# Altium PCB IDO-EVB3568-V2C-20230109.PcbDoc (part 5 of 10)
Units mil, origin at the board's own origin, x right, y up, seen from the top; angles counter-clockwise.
Board outline 5318 x 3544 mil, 2 copper layers (TOP, BOTTOM), stack 6.8 mil thick; 790 components, 626 nets, 2890 pads, 1922 vias.
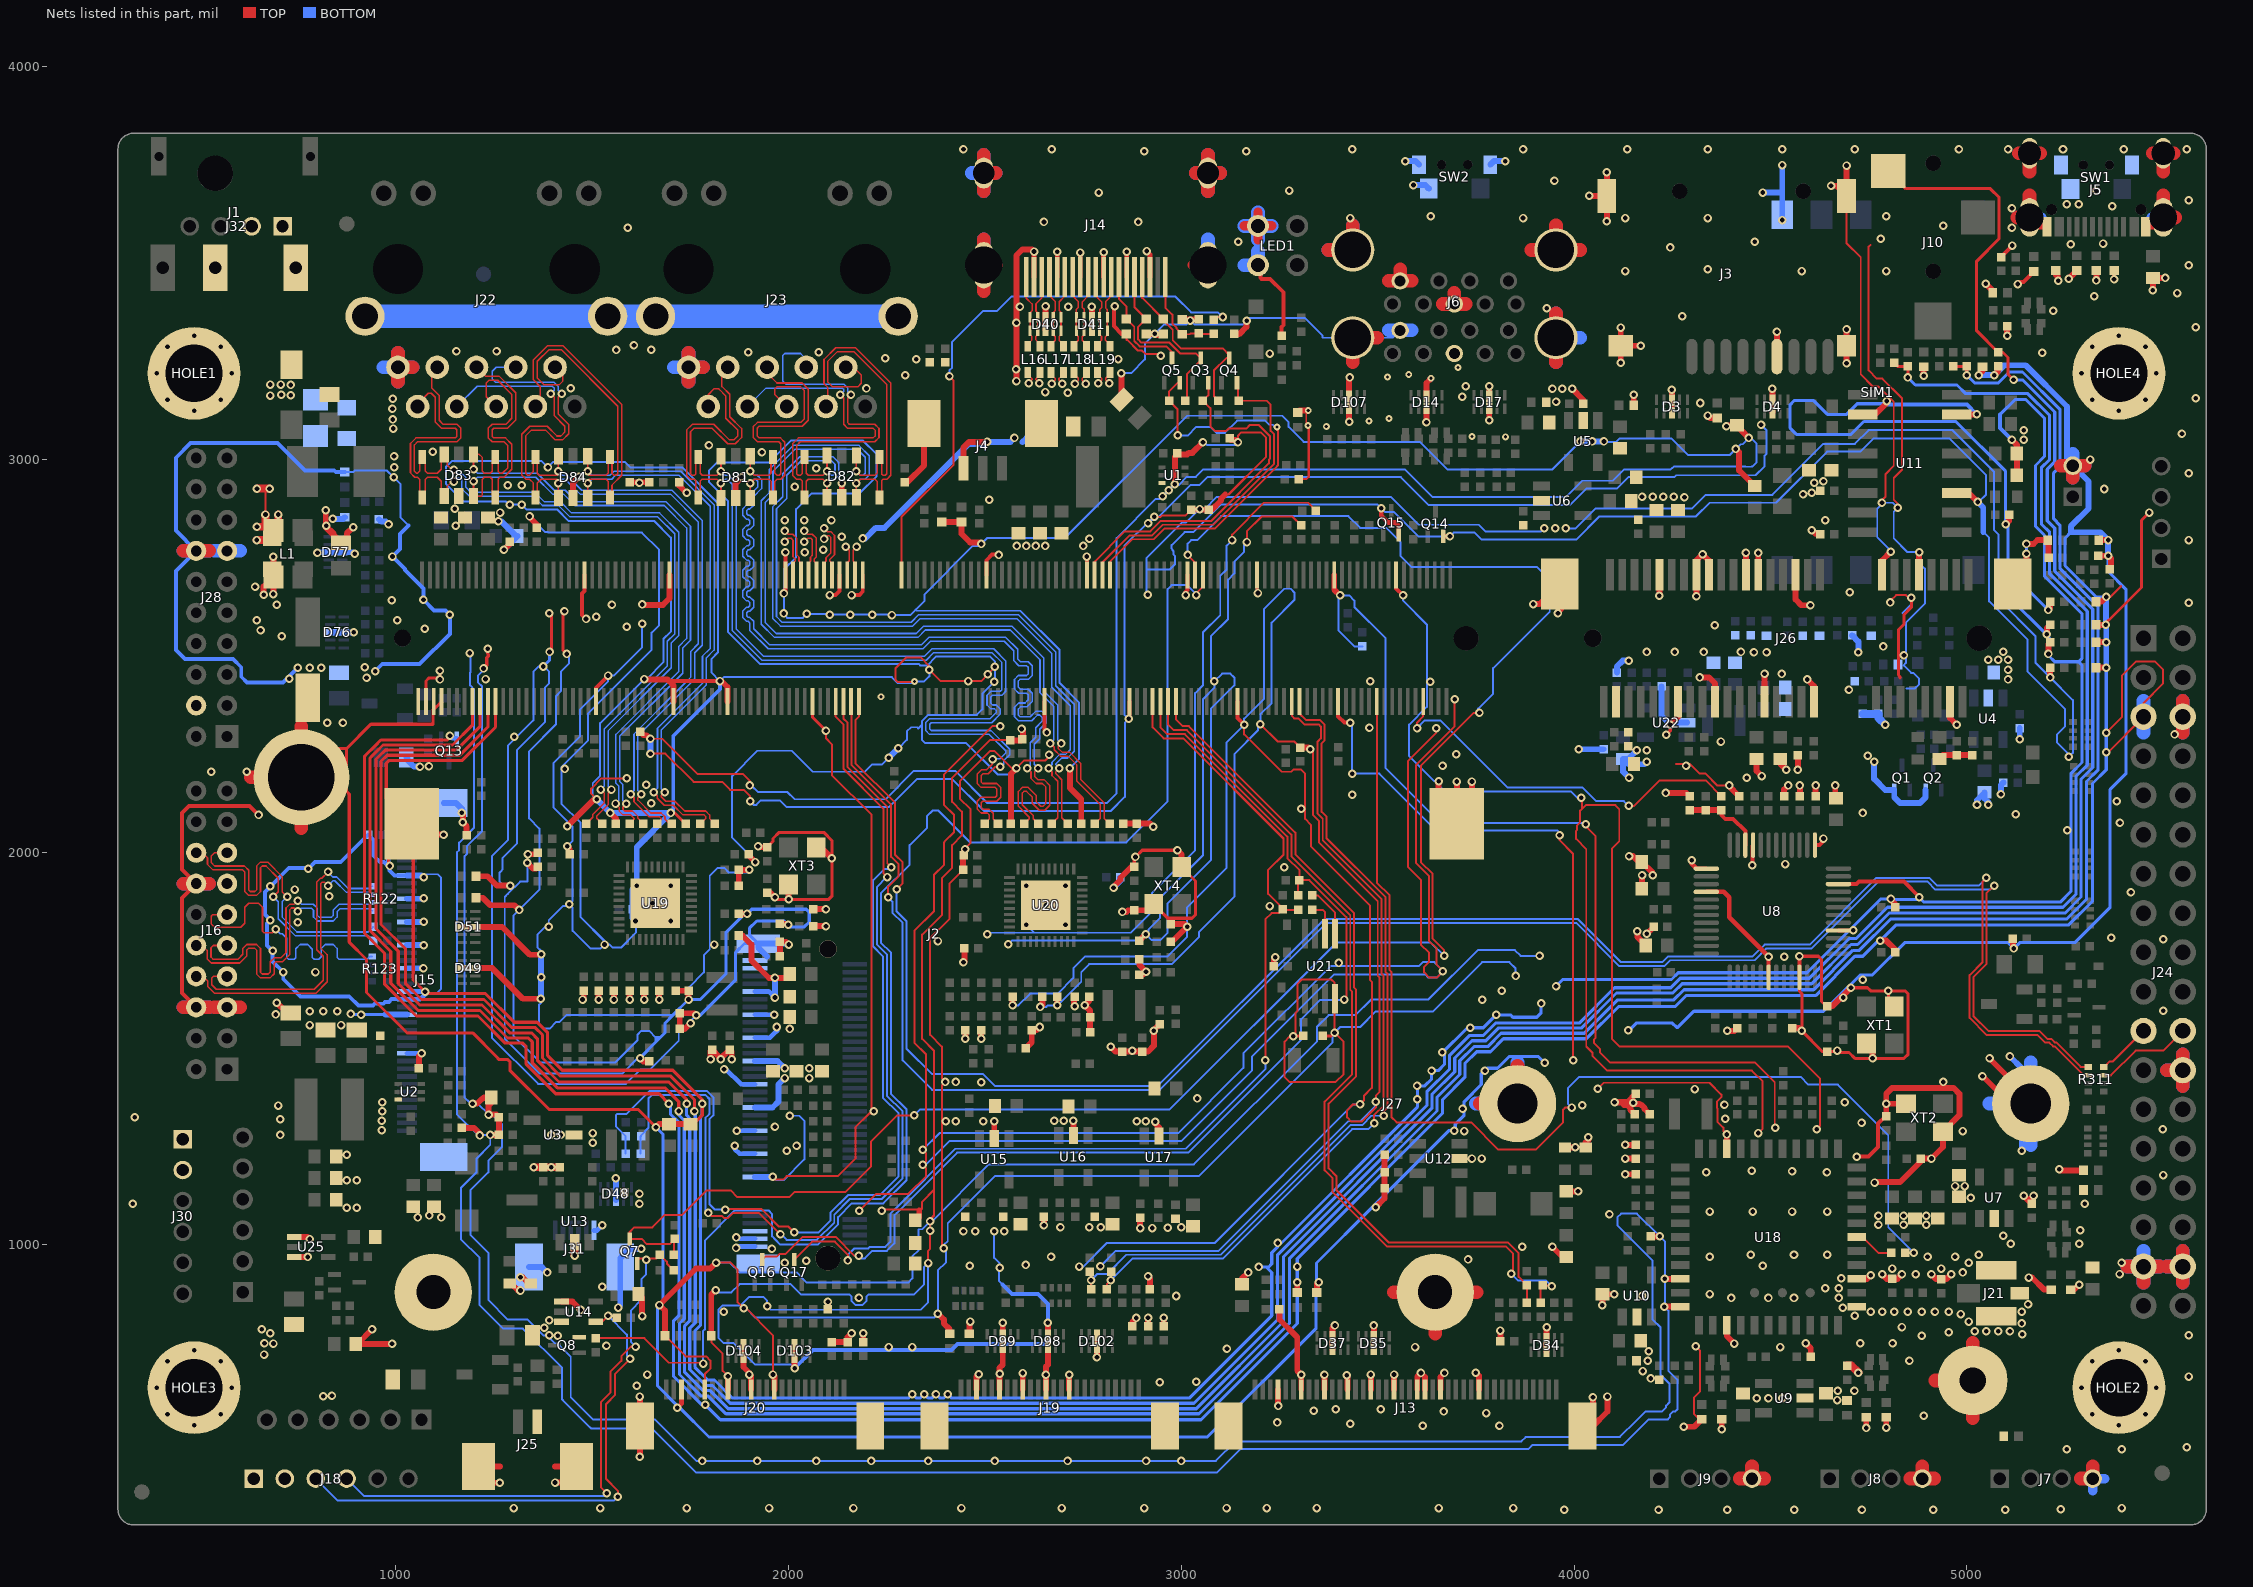
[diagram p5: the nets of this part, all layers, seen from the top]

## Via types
v1: diameter 21.65, hole 11.81, TOP to BOTTOM, 1878 vias
v2: diameter 17.72, hole 7.87, TOP to BOTTOM, 44 vias

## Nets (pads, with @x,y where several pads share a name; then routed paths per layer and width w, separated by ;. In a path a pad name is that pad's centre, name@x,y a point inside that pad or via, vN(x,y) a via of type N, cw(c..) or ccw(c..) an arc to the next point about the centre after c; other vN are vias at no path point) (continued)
GND: (continued)
  BOTTOM w12: v1(984,1965) 980.49,1968.51 980.49,1985.49 994.8,1999.8 J15.37@1027.99,1999.8 ; J15.11@1027.99,1487.99 v1(1065,1487.99) ; J15.18@1027.99,1625.79 1062,1625.79 1074,1637.79 v1(1074,1645) 1073.53,1645.47 J15.19@1027.99,1645.47 ; v1(1137.41,2296.22) 1143.13,2290.5 Q13.2@1154.68,2290.5 ; J31.6@1504.21,1037.01 1512.01,1037.01 v1(1525,1050) ; v1(1835.43,1447.71) 1840.29,1447.71 1878.79,1409.21 J27.33@1913.98,1409.21 ; v1(1863,1253) 1863,1244.05 1875,1232.05 J27.51@1913.98,1232.05 ; v1(1865.9,992.36) 1866,992.36 1869.47,995.83 J27.75@1913.98,995.83 ; v1(1866.65,1019) 1870,1019 1873.49,1015.51 J27.73@1913.98,1015.51 ; v1(1868,1291.1) J27.45@1913.98,1291.1 ; J27.21@1913.98,1527.32 1952.32,1527.32 1970,1545 v1(1970,1555) ; J27.15@1913.98,1586.38 v1(1963.62,1586.38) ; J27.9@1913.98,1645.43 1949.57,1645.43 v1(1965,1630)
  BOTTOM w15: v1(800,2763) 801,2764 D77.3@830.44,2764 D77.8@861.56,2764 891,2764 v1(895,2760) ; D76.3@834.44,2560 D76.8@865.56,2560 v1(892,2560) ; v1(839.1,2849.1) 865,2849.1 869,2853.1 D80.2@870,2853.1 ; R385.2@956.72,2848 962.72,2842 974,2842 v1(981,2835) ; 973.58,1586.42 J15.16@1027.99,1586.42 ; C245.1@1026.48,2241 1029.48,2238 1029.48,2234.52 1046,2218 v1(1061,2218) ; J15.22@1027.99,1704.53 v1(1070,1704.53) ; J15.25@1027.99,1763.58 v1(1071,1763.58) ; J15.28@1027.99,1822.64 v1(1071,1822.64) ; J15.31@1027.99,1881.69 1069,1881.69 1070,1882.69 v1(1071,1882.69) ; J15.34@1027.99,1940.75 1064.25,1940.75 1069,1936 v1(1071,1936) ; 1087,959 1095.08,950.92 J2.N4@1095.08,879.65 1095.08,860.92 1142,814 ; J15.42@1121.5,2125.79 1152.21,2125.79 1170,2108 v1(1170,2076) ; v1(1261,2843) 1268,2843 1306,2805 C26.1@1309.56,2805 1309.56,2804.56 v1(1275,2770) ; J31.7@1338.86,943.5 1371.5,943.5 v1(1385,930) ; v1(1369,1627) 1369,1676 1369.5,1676.5 v1(1369.5,1681.5) v1(1369.5,1740) ; v1(1511,2135) v1(1546,2100) v1(1700,2100) 1613,2013 v1(1613,1915) 1602.72,1904.72 C138.1@1602.72,1855 1602.72,1832.28 v1(1610,1825) ; D48.3@1560,1114.44 D48.8@1560,1145.56 v1(1560,1170) ; v1(1566,840.65) 1571,845.65 1571,857.21 1571.14,857.36 J31.8@1571.14,943.5 1571.14,966.14 1595,990 v1(1625,990) ; v1(1648,2251) v1(1648,2289) ; J27.57@1913.98,1172.99 1957.99,1172.99 v1(1958.99,1173.99) ; J27.39@1913.98,1350.16 1958.97,1350.16 1973.61,1364.79 1973.61,1408.61 v1(1990,1425) ; J27.27@1913.98,1468.27 1971.73,1468.27 v1(1990,1450) ; 1945,1735 1922.84,1757.16 J27.G2@1922.84,1767.48 1997.52,1767.48 v1(2000,1765) ; v1(1965,1630) v1(1965,1680) ; v1(2189,2799) 2195,2799 2222,2826 2244,2826 2457,3039 2499,3039 v1(2505,3045) 2565,3045 v1(2575,3055) ; v1(2254.85,2240.34) v1(2279.25,2264.75) ; 2595,3044 2606,3055 ; v1(2827.22,1909.78) 2843.72,1926.28 C163.1@2843.72,1936 ; v1(3570,3760) 3596.4,3760 SW2.2@3605.4,3751 ; v1(3591.02,3698.98) 3621.05,3698.98 SW2.4@3630.05,3689.98 ; SW2.1@3786.6,3751 3795.6,3760 v1(3825,3760) ; v1(4012.28,2262.28) C206.1@4075,2262.28 ; v1(4016,3046) v1(4046,3046) v1(4076,3046) ; R345.1@4109,2457.72 4109,2472.86 4124,2487.86 v1(4139.14,2487.86) ; v1(4140,2190) 4125,2205 C205.1@4125,2237.44 ; v1(4160,2260) 4137.44,2237.44 C205.1@4125,2237.44 ; v1(4185,2230) 4179,2224 4138.44,2224 C205.1@4125,2237.44 ; C203.1@4223,2422.28 4223,2347 v1(4245,2325) 4250,2330 U22.2@4288.15,2330 ; v1(4480,3680) 4530,3680 ; v1(4530,3610) SIM1.C5@4530,3623.19 4530,3680 ; v1(4530,3750) 4530,3680 ; C185.2@4708,2552.28 4724,2536.28 v1(4724,2509) ; v1(4764,2230) 4764,2187 4792.49,2158.5 Q1.2@4815.31,2158.5 4815.31,2140 4830.31,2125 4880.31,2125 4895.31,2140 Q2.2@4895.31,2158.5 ; v1(5026,2121) 5026,2132.44 C33.2@5045,2151.44 ; v1(5028,2892) 5042,2878 5042,2816 ; v1(5030,3215) v1(5070,3215) 5095,3240 5150,3240 5255,3135 5255,2999.37 J11.2@5270,2984.37 5310,2944.37 5310,2875 5265,2830 5265,2815 5340,2815 v1(5360,2795) v1(5360,2755) ; C33.2@5045,2152.44 C33.2@5045,2151.44 ; v1(5055,2120.86) 5055,2127 5045,2137 C33.2@5045,2151.44 ; v1(5087,2148) 5087,2171.28 R36.1@5093,2177.28 ; v1(5110,1480) 5140.31,1449.68 v1(5140.31,1240.32) ; v1(5135,2288) R33.1@5135,2316.28 ; v1(5355,2470) v1(5355,2534.89) 5355,2578 v1(5354,2579) 5354,2649 v1(5355,2650)
  BOTTOM w20: R41.1@4735,2352.28 C35.1@4775,2352.28 4775,2342 v1(4792,2325)
  BOTTOM w24: 653.57,2191 H2.1@759,2191 ; 759,2085.57 H2.1@759,2191 ; 759,2296.43 H2.1@759,2191 ; 3891.66,3533.74 J6.22@3953.66,3533.74 ; 3953.66,3595.74 J6.22@3953.66,3533.74 ; 4015.66,3533.74 J6.22@3953.66,3533.74 ; 5129.3,3616.61 J5.H2@5159.92,3616.61 ; 5133.23,3780 J5.H4@5159.92,3780 ; 5159.92,3672.83 J5.H2@5159.92,3616.61 ; 5159.92,3733.63 J5.H4@5159.92,3780 ; 5186.61,3780 J5.H4@5159.92,3780 ; 5190.55,3616.61 J5.H2@5159.92,3616.61 ; 5289.89,405 J7.4@5320.51,405 ; 5320.51,374.38 J7.4@5320.51,405 ; 5320.51,435.62 J7.4@5320.51,405 ; 5351.13,405 J7.4@5320.51,405 ; 5469.45,3616.61 J5.H1@5500.08,3616.61 ; 5473.39,3780 J5.H3@5500.08,3780 ; 5500.08,3672.83 J5.H1@5500.08,3616.61 ; 5500.08,3733.63 J5.H3@5500.08,3780 ; 5526.77,3780 J5.H3@5500.08,3780 ; 5530.7,3616.61 J5.H1@5500.08,3616.61
  BOTTOM w35: 458.67,1605.08 J16.6@491.26,1605.08 523.85,1605.08 ; 458.67,1920.04 J16.14@491.26,1920.04 523.85,1920.04 ; 458.67,2767.44 J28.14@491.26,2767.44 523.85,2767.44 ; 537.41,2767.44 J28.13@570,2767.44 602.59,2767.44 ; 968,3235 J22.10@1005,3235 ; 1005,3198 J22.10@1005,3235 ; 1005,3272 J22.10@1005,3235 ; 1042,3235 J22.10@1005,3235 ; 1708,3235 J23.10@1745,3235 ; 1745,3198 J23.10@1745,3235 ; 1745,3272 J23.10@1745,3235 ; 1782,3235 J23.10@1745,3235 ; 2466.1,3494.92 J14.21@2496.73,3494.92 ; 2466.1,3729.57 J14.22@2496.73,3729.57 ; 2496.73,3560.98 J14.21@2496.73,3494.92 ; 2496.73,3683.2 J14.22@2496.73,3729.57 ; 2496.73,3775.94 J14.22@2496.73,3729.57 ; 2527.35,3494.92 J14.21@2496.73,3494.92 ; 2527.35,3729.57 J14.22@2496.73,3729.57 ; 3036.97,3494.92 J14.20@3067.6,3494.92 3067.6,3560.98 ; 3036.97,3729.57 J14.23@3067.6,3729.57 ; 3067.6,3683.2 J14.23@3067.6,3729.57 ; 3067.6,3775.94 J14.23@3067.6,3729.57 ; 3098.22,3729.57 J14.23@3067.6,3729.57 ; 3160,3495 LED1.4@3195,3495 3195,3530 ; 3160,3595 LED1.2@3195,3595 ; 3195,3560 LED1.2@3195,3595 ; 3195,3630 LED1.2@3195,3595 ; 3230,3595 LED1.2@3195,3595 ; 3374.34,3533.74 J6.21@3436.34,3533.74 3436.34,3595.74 ; 3528.2,3329.02 J6.13@3557.2,3329.02 3586.2,3329.02 ; 3576.27,879.65 J2.N3@3646.26,879.65 ; 3646.26,809.65 J2.N3@3646.26,879.65 ; 3646.26,949.64 J2.N3@3646.26,879.65 ; 3716.25,879.65 J2.N3@3646.26,879.65 ; 3750.48,1360 J27.G4@3855.91,1360 3855.91,1465.43 ; 3953.66,3248.12 J6.19@3953.66,3310.12 ; 3953.66,3372.12 J6.19@3953.66,3310.12 ; 4015.66,3310.12 J6.19@3953.66,3310.12 ; 4954.85,655 H1.1@5015,655 ; 5015,594.85 H1.1@5015,655 ; 5015,715.15 H1.1@5015,655 ; 5057.56,1360 J27.G3@5162.99,1360 ; 5075.15,655 H1.1@5015,655 ; 5162.99,1254.57 J27.G3@5162.99,1360 ; 5162.99,1465.43 J27.G3@5162.99,1360 ; 5270,2953.75 J11.2@5270,2984.37 ; 5270,3014.99 J11.2@5270,2984.37 ; 5300.62,2984.37 J11.2@5270,2984.37 ; 5409.53,945 J24.33@5450,945 ; 5450,904.53 J24.33@5450,945 ; 5450,985.47 J24.33@5450,945 ; 5450,2304.53 J24.5@5450,2345 5450,2385.47 ; 5490.47,945 J24.33@5450,945 ; 5509.53,945 J24.34@5550,945 ; 5509.53,1445 J24.24@5550,1445 ; 5550,904.53 J24.34@5550,945 ; 5550,985.47 J24.34@5550,945 ; 5550,1404.53 J24.24@5550,1445 ; 5550,1485.47 J24.24@5550,1445 ; 5550,2304.53 J24.6@5550,2345 5550,2385.47
  other v1: 3975,326 4215,326 4390,326 4561,326 4733,326 4915,326 5098,326 5239,327 1300,330 1520,330 1740,330 1950,330 2165,330 2440,330 2695,330 2905,330 3115,330 3217,330 3345,330 3655,330 3845,330 5395,330 5255,480 5395,480 5560,485 3615,540 3810,540 3430,545 3244,548 4890,565 3776,572 3668,576 3337,578 3393,582 3508,582 4670,605 4465,610 4495,610 4530,610 4671,629 4714,629 1613,641 2945,650 3038,652 4195,660 5565,665 1640,670 4175,679 4188,705 4854,705 4190,729 3116,736 2255,740 2315,740 3595,740 4525,740 1536,743 4729,750 4811,750 1412,769 4885,769 5565,770 5141,773 4954,778 5020,780 5050,780 5080,780 5110,780 1378,789 4835,791 5140,800 5005,805 1390,808 4715,820 4985,824 1835,830 4755,830 4785,830 4815,830 4850,830 4885,830 4919,830 4954,830 5140,830 4684,840 5156,849 4400,865 4495,865 4560,865 4674,865 2179,866 2987,870 4173,871 4345,875 4640,890 4674,890 1525,894 4680,915 4870,925 5389,926 4990,930 4810,940 4935,940 2461,947 4480,947 2604,949 1990,955 5005,955 5394,955 2045,960 3730,963 2668,970 4345,970 4900,970 4970,970 4450,975 4560,975 4645,975 5030,975 1957.47,990 3868,995 5112,1003 5286,1003 5093,1023 2445,1035 2475,1035 2549,1035 5289,1037 2926,1043 2965,1044 2692,1045 2765,1045 2795,1045 3000,1045 4775,1051 4839,1051 4897,1051 1055,1070 1115,1070 4775,1074 4839,1074 4897,1074 1085,1075 4090,1078 4345,1085 4455,1085 4555,1085 4645,1085 875,1095 900,1095 330,1105 1620,1105 5300,1105 5010,1120 1620,1130 4970,1150 4995,1150 875,1165 900,1165 5500,1178 4337,1185 4644,1185 4555,1188 4452,1189 3740,1220 3765,1220 875,1230 1995,1240 2020,1253 1501,1260 705,1280 1395,1280 1420,1280 1501,1285 3720,1290 4990,1290 964,1292 5499,1295 1965,1301 4732,1311 2400,1315 2425,1315 2495,1315 2886,1315 2909,1315 964,1316 2676,1316 2700,1316 705,1320 4385,1321 335,1325 965,1340 700,1355 4020.49,1355.31 4383,1357 965,1363 4689,1363 3040,1373 4307,1397 2490,1414 2425,1415 4940,1415 2052,1425 2052,1450 2003,1550 780,1560 860,1560 694,1587 780,1595 815,1595 850,1595 5500,1596 3766,1624 4685,1630 3816,1647 4735,1675 795,1695 3401,1718 4535,1734 1810,1765 2380.14,1773.86 5500,1778 5368,1782 2705,1815 750,1822 1700,1825 3225,1863 2655,1865 1653.17,1870 830,1888 5418,1898 742,1905 1700,1915 2605,1915 2705,1915 3262,1962 4538,1970 5256,2056 5390,2075 5125,2096.65 4735,2100 3305,2111 1650,2125 5382,2130 3435,2146 1637,2172 4440,2190 530,2205 620,2205 1430,2212 1084,2219 3665,2220 4285,2220 4748,2246 3700,2250 4185,2260 4374,2282 1301,2294 5529,2300 3479,2317 825,2330 865,2330 4700.04,2414.24 3634,2434 3481,2435 5105,2440 1228,2441 728,2442 925,2444 4529,2454 5105,2465 780,2470 810,2470 920,2471 5055,2490 5080,2490 5105,2490 4840,2502 4458,2509 4490,2509 4185,2510 4256,2510 4330,2510 4425,2510 5093,2511 4787,2524 709,2550 655,2565 1073,2569 1588,2574 4358,2578 645,2591 1003,2591 1510,2600 696,2630 1550,2630 5565,2635 989,2642 4702,2662 641,2676 2041,2764 2088,2770 2581,2780 2605,2780 2629,2780 2653,2780 2750,2780 5565,2795 2766,2798 2135,2803 3952,2825 1152,2831 2915,2838 1990,2845 2040,2845 2109,2845 4640,2845 1265,2865 1150,2875 2511,2898 4281,2904 4173,2905 4200,2905 4227,2905 4254,2905 4583,2912 4605,2915 5350,2925 2015,2931 1285,2935 1320,2935 4612,2941 4635,2945 5565,2965 2070,2978 996,2980 5314,3000 995,3008 1932,3019 1094,3020 1797,3036 5145,3050 5548,3066 5145,3075 993,3079 992,3102 991,3129 4321,3144 3954,3147 992,3155 5583,3156 3715,3160 2711,3170 2653,3172 3945,3180 3970,3180 2198,3181 1445,3182 3724,3187 2297,3215 2579,3230 2325,3255 2839,3256 2246,3258 3225,3270 5192,3272 1897,3273 2077,3273 1154,3276 1256,3276 1561,3279 1650,3280 1606,3291 5583,3337 4275,3365 5220,3379 3930,3385 2589,3389 2712,3389 5325,3416 5536,3424 4130,3480 4580,3480 4795,3480 4340,3485 5565,3495 4245,3540 5265,3548 5347,3550 3145,3555 4460,3555 4781,3562 1590,3590 5115,3590 4940,3595 2650,3605 2890,3605 3430,3615 3870,3615 4130,3615 4340,3615 3635,3620 4795,3620 5115,3640 5370,3645 5255,3650 5285,3650 5565,3660 2790,3680 3275,3685 5330,3685 3950,3710 2905,3785 3165,3785 2445,3790 2670,3790 3435,3790 3870,3790 4135,3790 4340,3790 4530,3790 4715,3790 4980,3790 5105,3790 5245,3790 5400,3790 5560,3790
  other v2: 2235,2396 3825,3058 3740,3059 3369,3084 3478,3098 3529,3105 3525,3210 3579,3217 3704,3234
GND_EARTH: C261.2 HOLE1.1 HOLE2.1 HOLE3.1 HOLE4.1 J22.SH1 J22.SH2 J23.SH1 J23.SH2 R419.2 | length 1384
  BOTTOM w5: HOLE1.1@459.65,3219.65 HOLE1.1@485.85,3219.65
  BOTTOM w60: J22.SH1@921.1,3364.9 J22.SH2@1538.9,3364.9 J23.SH1@1661.1,3364.9 J23.SH2@2278.9,3364.9
GND_IN: C2.1 C256.1 C257.1 D1.C J1.2 J1.3 J18.1 J18.2 J30.1 J30.2 J32.1 J32.2 L1.2 R2.1 | length 285.1
  TOP w5: v1(667.6,2860) 667.6,2915.6 v1(678,2926)
  TOP w20: v1(645,2795) 667.6,2795 687.6,2815 L1.2@687.6,2819.05 ; v1(645.95,2829.05) L1.2@677.6,2829.05 ; v1(646,2926) v1(678,2926) ; v1(667.6,2860) 667.6,2839.05 L1.2@677.6,2829.05 ; v1(700,2860) 700,2830 689.05,2819.05 L1.2@687.6,2819.05 ; L1.2@677.6,2829.05 L1.2@687.6,2819.05
  other v1: 815,615 837,616 664,721 688,749 665,750 680,775 658,785 680,3163 732,3164 708,3165 732,3190 680,3191 707,3191
HDMI_TX_CEC_PORT: D44.1 J14.13 Q5.3 | length 302.3
  TOP w5: J14.13@2841.22,3465 2841.22,3408.78 2860,3390 D44.1@2860,3357.9 2860.1,3357.9 2880,3338 2880,3301.86 2893.86,3288 2962,3288 2976,3274 Q5.3@2976,3258.5
HDMI_TX_CLKN: J2.147 L19.2 | length 112.2
  TOP w4: J2.147@2168.89,2706.42 2168.89,2737.11 2164.05,2741.95 2164.05,2769 v1(2172.7,2777.64) ; v1(2816,3194) 2807.43,3202.57 2807.43,3207.22 2817.75,3217.53 L19.2@2817.75,3221.53
HDMI_TX_CLKN_: D41.5 D41.6 J14.12 L19.3 | length 191.1
  TOP w4: L19.3@2817.75,3288.47 2817.75,3292.25 2806.53,3303.47 2806.53,3312.52 2811.37,3317.37 D41.5@2811.37,3327.78 D41.6@2811.37,3362.22 2811.37,3381.63 2806.85,3386.15 2806.85,3401.85 2821.54,3416.54 J14.12@2821.54,3465
HDMI_TX_CLKP: J2.149 L19.1 | length 112.6
  TOP w4: v1(2145.41,2777.64) 2154.05,2769 2154.05,2742.05 2149.21,2737.21 J2.149@2149.21,2706.42 ; L19.1@2786.25,3221.53 2786.25,3217.75 2797.43,3206.56 2797.43,3202.73 v1(2788.71,3194)
HDMI_TX_CLKP_: D41.4 D41.7 J14.10 L19.4 | length 191
  TOP w4: J14.10@2782.17,3465 2782.17,3416.7 2796.85,3402.01 2796.85,3386.85 2791.68,3381.68 D41.7@2791.68,3362.22 D41.4@2791.68,3327.78 2791.68,3318.32 2796.53,3313.48 2796.53,3303.53 2786.25,3293.25 L19.4@2786.25,3288.47
HDMI_TX_D0N: J2.155 L18.2 | length 161.7
  TOP w4: v1(2090,2797.83) 2098.64,2806.47 2102.64,2806.47 2106.64,2802.47 2106.64,2761.64 2095,2750 2095,2741 2090.15,2736.15 J2.155@2090.15,2706.42 ; v1(2756.29,3193) 2747.17,3202.12 2747.17,3206.17 2758.25,3217.25 L18.2@2758.25,3221.53
HDMI_TX_D0N_: D41.2 D41.9 J14.9 L18.3 | length 191.2
  TOP w4: L18.3@2758.25,3288.47 2758.25,3292.75 2747.47,3303.53 2747.47,3312.47 2752.32,3317.32 D41.2@2752.32,3327.78 D41.9@2752.32,3362.22 2752.32,3382.44 2747.47,3387.28 2747.47,3401.48 2762.48,3416.48 J14.9@2762.48,3465
HDMI_TX_D0P: J2.153 L18.1 | length 177.6
  TOP w4: v1(2090,2825.12) 2098.65,2816.47 2106.79,2816.47 2116.64,2806.61 2116.64,2757.5 2105,2745.85 2105,2741 2109.84,2736.16 J2.153@2109.84,2706.42 ; L18.1@2726.75,3221.53 2726.75,3217.25 2737.17,3206.83 2737.17,3201.17 v1(2729,3193)
HDMI_TX_D0P_: D41.1 D41.10 J14.7 L18.4 | length 190.9
  TOP w4: J14.7@2723.11,3465 2723.11,3416.89 2737.47,3402.52 2737.47,3387.28 2732.63,3382.43 D41.10@2732.63,3362.22 D41.1@2732.63,3327.78 2732.63,3317.37 2737.47,3312.53 2737.47,3303.47 2726.75,3292.75 L18.4@2726.75,3288.47
HDMI_TX_D1N: J2.159 L17.2 | length 155
  TOP w4: v1(2040,2791.1) 2048.9,2800 2055.86,2800 2060,2795.86 2060,2756 2055.63,2751.63 2055.63,2740.62 2050.78,2735.78 J2.159@2050.78,2706.42 ; v1(2696.93,3193.25) 2688.42,3201.76 2688.42,3206.42 2699.25,3217.25 L17.2@2699.25,3221.53
HDMI_TX_D1N_: D40.5 D40.6 J14.6 L17.3 | length 191
  TOP w4: L17.3@2699.25,3288.47 2699.25,3292.75 2688.53,3303.47 2688.53,3312.53 2693.37,3317.37 D40.5@2693.37,3327.78 D40.6@2693.37,3362.22 2693.37,3375.02 2688.74,3379.64 2688.74,3402.02 2703.43,3416.7 J14.6@2703.43,3465
HDMI_TX_D1P: J2.157 L17.1 | length 171.3
  TOP w4: v1(2040,2818.16) 2048.16,2810 2060,2810 2070,2800 2070,2751.86 2065.63,2747.48 2065.63,2740.38 2070.47,2735.53 J2.157@2070.47,2706.42 ; L17.1@2667.75,3221.53 2667.75,3217.25 2678.42,3206.58 2678.42,3202.02 v1(2669.64,3193.25)
HDMI_TX_D1P_: D40.4 D40.7 J14.4 L17.4 | length 191.2
  TOP w4: J14.4@2664.06,3465 2664.06,3416.94 2678.74,3402.26 2678.74,3379.64 2673.68,3374.58 D40.7@2673.68,3362.22 D40.4@2673.68,3327.78 2673.68,3317.32 2678.53,3312.47 2678.53,3303.53 2667.75,3292.75 L17.4@2667.75,3288.47
HDMI_TX_D2N: J2.163 L16.2 | length 154.4
  TOP w4: v1(1990,2790.84) 1998.64,2799.49 2006.3,2799.49 2011,2794.79 2011,2752.86 2016.26,2747.6 2016.26,2741.26 2011.41,2736.41 J2.163@2011.41,2706.42 ; v1(2638.31,3194.27) 2629.5,3203.08 2629.5,3205.5 2640.25,3216.25 L16.2@2640.25,3221.53
HDMI_TX_D2N_: D40.2 D40.9 J14.3 L16.3 | length 191
  TOP w4: L16.3@2640.25,3288.47 2640.25,3293.75 2629.47,3304.53 2629.47,3313.47 2634.32,3318.32 D40.2@2634.32,3327.78 D40.9@2634.32,3362.22 2634.32,3373.68 2629.68,3378.31 2629.68,3396.68 2644.37,3411.37 J14.3@2644.37,3465
HDMI_TX_D2P: J2.161 L16.1 | length 170.9
  TOP w4: v1(1990,2818.13) 1998.65,2809.49 2010.44,2809.49 2021,2798.93 2021,2757 2026.26,2751.74 2026.26,2740.74 2031.1,2735.9 J2.161@2031.1,2706.42 ; L16.1@2608.75,3221.53 2608.75,3216.25 2619.5,3205.5 2619.5,3202.75 v1(2611.02,3194.27)
HDMI_TX_D2P_: D40.1 D40.10 J14.1 L16.4 | length 191.2
  TOP w4: J14.1@2605,3465 2605,3411 2619.68,3396.32 2619.68,3378.68 2614.63,3373.63 D40.10@2614.63,3362.22 D40.1@2614.63,3327.78 2614.63,3318.37 2619.47,3313.53 2619.47,3304.47 2608.75,3293.75 L16.4@2608.75,3288.47
HDMI_TX_HPD_PORT: D46.1 J14.19 R107.2 R108.2 | length 245.9
  TOP w5: J14.19@2959.33,3465 2959.33,3386.67 2977,3369 2977,3346.14 2988,3335.14 2988,3333.1 D46.1@3002,3319.1 3021.1,3319.1 3023.28,3321.28 R108.2@3044,3321.28 3045,3320.28 R107.2@3083,3320.28
HDMI_TX_HPDIN: J2.143 R107.1 | length 1438.7
  TOP w5: J2.143@2287,2706.42 2287,2853.71 2420,2986.71 2420,3201 2409.39,3211.61 v1(2409.39,3212.12) ; R107.1@3083,3355.72 3090.28,3363 v1(3105,3363)
  BOTTOM w5: v1(2409.39,3212.12) 2409.39,3227.02 2416,3233.63 2416,3299.43 2494.57,3378 2530,3378 2553.43,3401.43 2567,3415 2985,3415 3025,3375 3093,3375 v1(3105,3363)
HDMI_TXDDC_SCL_PORT: D45.1 J14.15 Q3.3 R104.1 | length 483.1
  TOP w5: J14.15@2880.59,3465 2880.59,3387.31 D45.1@2910,3357.9 2890,3337.9 2890,3306 2898,3298 2969.74,3298 2997.74,3270 3037.5,3270 Q3.3@3049,3258.5 3049,3252.67 3014.66,3218.33 3014.66,3154.39 R104.1@3010,3149.72
HDMI_TXDDC_SDA_PORT: D47.1 J14.16 Q4.3 R106.2 | length 494.6
  TOP w5: J14.16@2900.28,3465 2900.28,3411.62 D47.1@2954,3357.9 2954,3355 2978,3331 2978,3303.88 2998.88,3283 3105,3283 3122.22,3265.78 3122.22,3258.71 Q4.3@3122,3258.5 3114.5,3258.5 3083,3227 3083,3161 3094,3150 R106.2@3094,3149.72
HDMITX_CEC_M0: J2.89 Q5.2 R109.1 | length 1106.6
  TOP w5: J2.89@2818.5,2706.42 2818.5,2740.5 2875,2797 2929.57,2797 2956.57,2824 3085,2824 3240.14,2979.14 3246,2985 3246,3073 3243.85,3075.15 v2(3243.85,3083.36) ; v1(2991,3062) 2990,3063 2990,3128.72 R109.1@2969,3149.72 2969,3173.82 2990.68,3195.5 Q5.2@2995.68,3195.5
  BOTTOM w5: v1(2991,3062) 2993,3062 2994,3061 3016,3061 3038,3083 3074,3083 3089,3068 3111,3068 3142,3099 3213,3099 3223.38,3088.62 3232.38,3088.62 3237.64,3083.36 v2(3243.85,3083.36)
HOLE1: J27.76
HOLE2: J27.77
HOST_WAKE_BT: R394.2 U18.6 | length 104.4
  TOP w5: U18.6@4719.41,1020 4735,1020 4775,980 R394.2@4807.28,980
HOST_WAKE_BT_H_GPIO1_D3: J2.20 R394.1 | length 2922.2
  TOP w5: J2.20@3497.63,2383.58 3497.63,1922.37 3530,1890 3530,1700 3535,1695 3535,1325 3548,1312 3738,1312 3807,1243 3902.86,1243 3971.83,1311.97 3971.83,1344.83 3977,1350 v1(3994,1350) ; R394.1@4842.72,980 v1(4865,980)
  BOTTOM w5: v1(3994,1350) 3984,1360 3984,1399 4013,1428 4577,1428 4596.67,1408.33 4671.53,1408.33 4800,1279.86 4800,1045 v1(4865,980)
HP_SNS: J2.244 J10.1 R81.1 | length 9107.2
  TOP w8: J2.244@1214.17,2383.58 1214.17,2321.17 1153,2260 993.77,2260 972.23,2260 956.62,2244.39 948.96,2236.74 948.96,1805.04 1005.81,1748.19 1005.81,1665.81 1060.62,1611 1219,1611 1289.85,1540.15 1331.84,1540 1345,1540 1360,1525 1360,1470 1415,1415 1695,1415 1740,1370 v1(1740,1360) ; J10.1@4800,3735 4845,3690 5060,3690 5082,3668 5082,3562 5025,3505 5025,3327.72 R81.1@5080,3272.72 5092.28,3272.72 5105,3260 5105,3217 v1(5119,3203)
  BOTTOM w8: v1(1740,1360) 1740,1330 1748,1322 1748,807 1735,794 1735,676 1782,629 1800,629 1846,583 3038,583 3260,805 3260,970 3638,1348 3638,1383 3696,1441 3696,1476 3740,1520 3775,1520 3807,1552 4018.39,1552 4107.88,1641.49 4251.49,1641.49 4275,1665 4605,1665 4705,1765 4722,1765 4802,1845 5250,1845 5291,1886 5291,2186 5320.79,2215.79 5320.79,2619.21 5224,2716 5224,2825 5205,2844 5205,2975 5224,2994 5224,3121 5142,3203 v1(5119,3203)
HPL_OUT: C72.2 J2.242 R84.1 | length 8547
  TOP w8: J2.242@1233.85,2383.58 1233.85,2318.85 1162,2247 988.38,2247 977.62,2247 961.96,2231.35 961.96,1978.33 962,1978.3 962,1816 1024.5,1753.5 1024.5,1665.5 1065,1625 1224,1625 1295.5,1553.5 1354.5,1553.5 1373,1535 1373,1476 1419,1430 1700,1430 1760,1370 v1(1760,1340) ; C72.2@4815,3246.28 4824,3237.28 R84.1@4850,3237.28 v1(4850,3209)
  BOTTOM w8: v1(1760,1340) 1762,1338 1762,802 1748,788 1748,683 1789,642 1806,642 1851,597 3032,597 3245,810 3245,975 3625,1355 3625,1390 3683,1448 3683,1483 3733,1533 3768,1533 3800,1565 4013,1565 4103,1655 4246,1655 4270,1679 4599,1679 4700,1780 4718,1780 4798,1860 5245,1860 5278,1893 5278,2193.35 5306.65,2222 5306.65,2613.35 5211,2709 5211,2815 5190,2836 5190,2979 5211,3000 5211,3112.23 5155.23,3168 4997,3168 4975,3190 4869,3190 v1(4850,3209)
HPR_OUT: C75.2 J2.246 R82.1 | length 8517.1
  TOP w8: 951.22,2257.38 936,2242.16 934,2240.16 934,1800 986.62,1747.38 986.62,1666.61 1056.23,1597 1214,1597 1283.85,1527.15 1337.04,1526.96 1347,1517 1347,1464 1411,1400 1685,1400 1720,1365 v1(1720,1341) ; 951.23,2257.38 966.85,2273 999.15,2273 1144.04,2273 1194.48,2323.44 J2.246@1194.48,2383.58 ; C75.2@4965,3237.28 R82.1@5000,3237.28 v1(5000,3215)
  BOTTOM w8: v1(1720,1341) 1720,1331 1734,1317 1734,812 1722,800 1722,670 1777,615 1795,615 1840,570 3045,570 3275,800 3275,965 3651,1341 3651,1376 3709,1434 3709,1469 3745,1505 3780,1505 3814,1539 4026,1539 4111,1624 4254,1624 4280,1650 4610,1650 4710,1750 4726,1750 4806,1830 5255,1830 5305,1880 5305,2180 5333.93,2208.93 5333.93,2626.07 5237,2723 5237,2833 5221,2849 5221,2966 5237,2982 5237,3128 5142,3223 5108,3223 5080,3195 5020,3195 v1(5000,3215)
HUB_RST: C48.2 R53.2 R66.1 U8.34 | length 206
  TOP w10: R53.2@4375,2107.28 4375,2095 4385,2085 4405,2085 4436.1,2053.9 U8.34@4436.1,2018.3
  TOP w15: C48.2@4295,2107.28 R66.1@4335,2107.28 R53.2@4375,2107.28
HUB_RST_GPIO1_A4_D: J2.8 R53.1 | length 990.5
  TOP w5: v1(3600,2316) 3600,2330 3615.74,2345.74 J2.8@3615.74,2383.58 ; v1(4139,2118) 4153,2118 4218,2183 4334.72,2183 R53.1@4375,2142.72
  BOTTOM w5: v1(3600,2316) 3619,2335 3660,2335 3830,2165 4021,2165 4056,2130 4127,2130 v1(4139,2118)
I2C1_SCL: J2.146 R311.2 | length 4807.7
  TOP w5: J2.146@2178.74,2383.58 2178.74,2345 2170,2336.26 2170,2227 2271,2126 2271,1993 2290,1974 2290,1920.92 v1(2275.04,1905.96) ; v1(5050,1935) 5040,1925 5040,1720 5007,1687 5007,1578 5050,1535 5180,1535 5199.99,1515.01 5210.51,1515.01 5219.59,1505.93 5223.45,1505.93 5297.53,1431.84 R311.2@5309.31,1431.84
  BOTTOM w5: v1(2275.04,1905.96) 2275.04,1880.04 2275,1880 2275,1849.14 2300,1824.14 2300,1500 2365,1435 2495,1435 2525,1405 2940,1405 3365,1830 4009.43,1830 4119.43,1720 4225,1720 4240,1735 4455,1735 4485,1765 4600,1765 4770,1935 4905,1935 4925,1915 5030,1915 v1(5050,1935)
I2C1_SCL_: J24.22 R311.7 | length 248.2
  TOP w5: R311.7@5348.69,1431.84 5367.03,1431.84 5430.19,1495 5500,1495 J24.22@5550,1545
I2C1_SDA: J2.148 R311.1 | length 4823.9
  TOP w5: J2.148@2159.05,2383.58 2160,2382.63 2160,2222 2261,2121 2261,1988 2280,1969 2280,1939 2253.33,1912.33 v1(2253.33,1885) ; v1(5070,1915) 5050,1895 5050,1878.43 5050,1715 5017,1682 5017,1583 5055,1545 5185,1545 5204.99,1525.01 5214.65,1525.01 5223.73,1515.92 5227.59,1515.92 5290.02,1453.5 R311.1@5309.31,1453.5
  BOTTOM w5: v1(2253.33,1885) 2253.33,1884.67 2264,1874 2264,1846 2290,1820 2290,1470.14 2365.14,1395 2945,1395 3370,1820 4005.28,1820 4115.28,1710 4230,1710 4245,1725 4460,1725 4490,1755 4605,1755 4775,1925 4900,1925 4920,1905 5060,1905 v1(5070,1915)
I2C1_SDA_: J24.21 R311.8 | length 139.2
  TOP w5: R311.8@5348.69,1453.5 5350.69,1453.5 5364.55,1467.36 5372.36,1467.36 J24.21@5450,1545
I2C2_SCL_M0: J2.150 R111.1 R115.1 | length 2560.8
  TOP w5: v1(1838.43,1089.92) 1839.51,1091 1931,1091 1975,1047 1999,1047 v1(2014,1032) ; J2.150@2139.37,2383.58 2139.37,2340.63 2150,2330 2150,2217 2251,2116 2251,1971.82 v1(2261.23,1961.59)
  BOTTOM w5: R115.1@1585,1232.72 R111.1@1585,1277.28 1560,1302.28 1560,1330 1564,1334 1570.71,1334 1587.28,1334 1644.96,1391.67 1784.18,1391.67 ; 1784.19,1391.68 1792.47,1391.68 1808.33,1375.82 1808.33,1329.88 1798,1319.55 1798,1104.31 1812.39,1089.92 v1(1838.43,1089.92) ; v1(2014,1032) 2076,1032 2106,1062 2106,1082 2151,1127 2232,1127 2280,1175 2280,1335 2240,1375 2240,1735 2215,1760 2215,1929 2243,1957 2254.41,1957 2259,1961.59 v1(2261.23,1961.59)
I2C2_SDA_M0: J2.152 R112.1 R116.1 | length 2525.4
  TOP w5: v1(1795,1081.39) 1795.39,1081.39 1803.45,1073.33 1830.65,1073.33 1834.98,1069 1845.92,1069 1857.92,1081 1925,1081 v1(1979,1027) ; J2.152@2119.68,2383.58 2119.68,2345.32 2140,2325 2140,2212 2241,2111 2241,1947 v1(2251.04,1936.96)
  BOTTOM w5: R116.1@1623,1232.72 1623,1276.28 R112.1@1624,1277.28 1624,1279 1643,1298 1643,1373 1651.67,1381.67 1788.33,1381.67 1798.33,1371.67 1798.33,1334.02 1793.86,1329.55 1788,1323.7 1788,1088.39 v1(1795,1081.39) ; v1(1979,1027) 1981,1027 1995,1013 2072,1013 2116,1057 2116,1077 2156,1117 2237,1117 2290,1170 2290,1340 2250,1380 2250,1740 2225,1765 2225,1912 2249,1936 2250.08,1936 v1(2251.04,1936.96)
I2C3_SCL_M1: J2.74 R92.1 R96.1 | length 2264.3
  TOP w5: J2.74@2966.14,2383.58 2966.14,2324.86 2980,2311 3014,2311 3280,2045 3280,1990 3430,1840 3430,1650 3435,1645 3435,1435 3365,1365 3365,1190 3385,1170 3385,1134.57 3517.39,1002.18 3523.24,996.33 3826.53,996.33 3845,977.86 3845,932 v1(3840,927) ; R96.1@3915,852.72 3915,892.28 R92.1@3920,897.28 3940.72,897.28 v1(3942.72,895.28)
  BOTTOM w5: v1(3840,927) 3857,910 3928,910 v1(3942.72,895.28)
I2C3_SDA_M1: J2.72 R93.1 R97.1 | length 2145.7
  TOP w5: J2.72@2985.82,2383.58 2985.82,2339.18 3004,2321 3019,2321 3290,2050 3290,1995 3440,1845 3440,1655 3445,1650 3445,1430 3375,1360 3375,1195 3395,1175 3395,1138.71 3527.39,1006.33 3830.67,1006.33 3858.64,978.36 3858.64,918.64 R93.1@3880,897.28 R97.1@3880,852.72
I2C4_SCL_M0: J2.42 R152.1 R155.1 | length 2100.3
  TOP w5: R152.1@2810,887.72 2810,900 v1(2820,910) 2821,911 R155.1@2821,932.28 ; J2.42@3281.1,2383.58 3281.1,2347 3287.05,2341.05 3297.95,2341.05 3313.31,2325.69 3349.31,2325.69 3355,2320 3355,2290 3347,2282 3347,2098 3360,2085 3360,2030 3510,1880 3510,1690 3515,1685 3515,1355 3491,1331 v1(3491,1310)
  BOTTOM w5: v1(2820,910) 2875,965 3105,965 3435,1295 3476,1295 v1(3491,1310)
I2C4_SDA_M0: J2.40 R153.1 R154.1 | length 2143.7
  TOP w5: R154.1@2767,932.28 2770,929.28 v1(2770,910) R153.1@2770,887.72 ; J2.40@3300.78,2383.58 3300.78,2353.22 3316.69,2337.31 3352.69,2337.31 3365,2325 3365,2285 3357,2277 3357,2103 3370,2090 3370,2035 3520,1885 3520,1695 3525,1690 3525,1350 3515,1340 v1(3515,1329)
  BOTTOM w5: v1(2770,910) 2786,926 2811,926 2860,975 3100,975 3430,1305 3460,1305 3484,1329 v1(3515,1329)
I2C5_SCL-HDMI: J2.93 Q3.2 R103.2 | length 951.1
  TOP w5: J2.93@2779.13,2706.42 2779.13,2740.13 2856,2817 2921,2817 2948,2844 3076.71,2844 3223,2990.29 3223,2999.86 3225.67,3002.53 3225.67,3059.79 3197.46,3088 3174,3088 3165,3079 3120,3079 3113.33,3072.33 3086.35,3072.33 3074,3084.67 3074,3130.72 R103.2@3055,3149.72 3068.68,3163.41 Q3.2@3068.68,3195.5
I2C5_SCL_M0: J2.78 Q17.3 R327.1 R328.2 | length 2702.7
  TOP w5: Q17.3@2014,962.5 2059.8,1008.29 2117.4,1008.29 2150.57,975.12 v1(2150.57,960.43) ; J2.78@2926.77,2383.58 2926.77,2318.23 2955,2290 3005,2290 3260,2035 3260,1994 3221,1955 3221,1894 3258,1857 R327.1@3258,1855.28 ; v1(3214,1470) 3214,1829 3230,1845 3247.72,1845 R327.1@3258,1855.28 ; R328.2@3297.28,1853 3260.28,1853 R327.1@3258,1855.28
  BOTTOM w5: v1(2150.57,960.43) 2152,961.86 2152,976 2167,991 2202.86,991 2206.86,995 2245.97,995 2259,1008.03 2259,1079.43 2264.86,1085.29 2270.71,1091.14 2424.58,1245.01 2432.86,1245.01 2441.14,1245 2983.86,1245 3008.71,1245 3011,1245 3214,1448 v1(3214,1470)
I2C5_SDA-HDMI: J2.91 Q4.2 R105.2 | length 859.7
  TOP w5: J2.91@2798.81,2706.42 2798.81,2737.81 2868,2807 2925.43,2807 2952.43,2834 3080.86,2834 3236,2989.14 3236,3064 3227.2,3072.8 3227.2,3139.52 3217.01,3149.72 R105.2@3146,3149.72 3144,3151.72 3144,3193.19 Q4.2@3141.68,3195.5
I2C5_SDA_M0: J2.76 Q16.3 R326.1 R329.2 | length 2912.5
  TOP w5: Q16.3@1933,962.5 1940.5,970 1970,970 1977.24,977.24 1992.24,977.24 2035.5,1020.5 2119.5,1020.5 2167.47,972.53 v1(2178.5,972.53) ; J2.76@2946.45,2383.58 2946.45,2318.55 2964,2301 3009,2301 3270,2040 3270,1985 3301.03,1953.97 3301.03,1929.31 R326.1@3300.72,1929 ; R329.2@3297.28,1890 3297.28,1925.56 R326.1@3300.72,1929 ; v1(3415,1625) 3420,1630 3420,1835 3326,1929 R326.1@3300.72,1929
  BOTTOM w5: v1(2178.5,972.53) 2185,966 2193.86,966 2212.86,985 2250.11,985 2269,1003.89 2269,1075.29 2274.86,1081.14 2428.72,1235 2436.99,1235 2979.71,1235 3012.86,1235 3017,1235 3305,1523 3305,1575 3354,1624 3414,1624 v1(3415,1625)
I2C_SCL_RTC: R328.1 U21.6 | length 90
  TOP w5: R328.1@3332.72,1853 3360,1853 3365.8,1847.2 U21.6@3365.8,1792.68
I2C_SDA_RTC: R329.1 U21.5 | length 130
  TOP w5: R329.1@3332.72,1890 3347,1890 3391.39,1845.61 U21.5@3391.39,1792.68
LAN0_A+: D57.A D84.4 J22.2 R223.2 | length 2157.1
  TOP w4: J22.2@1405,3235 1425,3215 1425,3200 1415,3190 1377.39,3190 1360,3207.39 1360,3250 1390,3280 1420.86,3280 1565,3135.86 1565,2964.14 1560.76,2959.9 1555.1,2959.9 1550,2965 1550,3001.18 D57.A@1545,3006.18 1540,3001.18 1540,2965 1535,2960 1492.4,2960 1488.4,2964 v1(1488.4,2970) D84.4@1488.4,3008.15 ; v1(1684,2153) 1675.5,2144.5 1675.5,2141.5 1687,2130 1710.14,2130 1735.14,2105 1788.64,2105 1798.5,2095.14 1798.5,2086.22 R223.2@1812,2072.72
  BOTTOM w4: v1(1488.4,2970) 1498.4,2960 1545,2960 1555,2970 1725,2970 1810,2885 1810,2514.86 1790.5,2495.36 1790.5,2426.36 1676,2311.86 1676,2161 v1(1684,2153)
LAN0_A-: D57.C D84.3 J22.3 R222.2 | length 2150.6
  TOP w4: J22.3@1355,3135 1367.67,3147.67 1367.67,3185.57 1350,3203.25 1350,3254.14 1385.86,3290 1425,3290 1575,3140 1575,2960 1550,2935 1550,2908.82 D57.C@1545,2903.82 1540,2908.82 1540,2945 1535,2950 1492.4,2950 1488.4,2946 v1(1488.4,2940) D84.3@1488.4,2901.85 ; v1(1656.35,2153) 1665.5,2143.85 1665.5,2137.36 1682.86,2120 1706,2120 1731,2095 1784.5,2095 1788.5,2091 1788.5,2086.22 R222.2@1775,2072.72
  BOTTOM w4: v1(1488.4,2940) 1498.4,2950 1549.14,2950 1559.14,2960 1720.86,2960 1800,2880.86 1800,2519 1780.5,2499.5 1780.5,2430.5 1666,2316 1666,2162.65 v1(1656.35,2153)
LAN0_B+: D56.A D84.6 J22.4 R221.2 | length 2156
  TOP w4: D84.6@1413.6,3008.15 v1(1413.6,2970) 1413.6,2964 1409.6,2960 1365,2960 1360,2965 1360,3001.18 D56.A@1355,3006.18 1350,3001.18 1350,2970 1340,2960 1335,2960 1330,2965 1330,3060 1345,3075 1380.86,3075 1405.86,3050 1424.14,3050 1440,3065.86 1440,3089.14 1413,3116.14 1413,3159.36 v1(1421.64,3168) ; v1(1625,2147.99) 1616,2138.99 1616,2133 1649,2100 1675.14,2100 1685,2090.14 1685,2084 1696.28,2072.72 R221.2@1702,2072.72
  BOTTOM w4: J22.4@1305,3235 1255,3235 1245,3225 1245,3205 1253.35,3196.65 1402.35,3196.65 1413,3186 1413,3176.64 v1(1421.64,3168) ; v1(1413.6,2970) 1423.6,2960 1435,2960 1473,2922 1703,2922 1780,2845 1780,2526.86 1761,2507.86 1761,2441.86 1751.57,2432.43 1616,2296.86 1616,2156.99 v1(1625,2147.99)
LAN0_B-: D56.C D84.1 J22.7 R220.2 | length 2153.7
  TOP w4: v1(1394.35,3168) 1403,3159.35 1403,3112 1430,3085 1430,3070 1420,3060 1410,3060 1385,3085 1340.86,3085 1320,3064.14 1320,2960.86 1330.86,2950 1340,2950 1350,2940 1350,2908.82 D56.C@1355,2903.82 1360,2908.82 1360,2940 1370,2950 1409.6,2950 1413.6,2946 v1(1413.6,2940) D84.1@1413.6,2901.85 ; v1(1597.36,2147.99) 1606,2139.35 1606,2128.86 1644.86,2090 1671,2090 1675,2086 1675,2082.72 R220.2@1665,2072.72
  BOTTOM w4: J22.7@1155,3135 1206.65,3186.65 1398.21,3186.65 1402.43,3182.43 1403,3181.86 1403,3176.65 v1(1394.35,3168) ; v1(1413.6,2940) 1423.6,2950 1430.86,2950 1468.86,2912 1698.86,2912 1770,2840.86 1770,2531 1751,2512 1751,2446 1727.43,2422.43 1608.93,2303.93 1606,2301 1606,2156.64 v1(1597.36,2147.99)
LAN0_C+: D55.A D83.4 J22.5 R425.2 | length 2151.1
  TOP w4: v1(1197.4,2975) D83.4@1197.4,3013.15 1211.85,3013.15 1220,3005 1220,2970 1225,2965 1240,2965 1245,2970 1245,2998.18 D55.A@1253,3006.18 1260,2999.18 1260,2970 1265,2965 1270.86,2965 1285,2979.14 1285,3035 1275,3045 1244.86,3045 1235,3054.86 1235,3080.14 1244.86,3090 1280,3090 1295,3105 1295,3165.86 1259.14,3201.72 1236.72,3201.72 1230,3195 1230,3160 J22.5@1255,3135 ; v1(1586.14,2123.58) 1578,2115.43 1578,2109 1582,2105 1602,2105 1616,2091 1616,2086.72 R425.2@1630,2072.72
  BOTTOM w4: v1(1197.4,2975) 1207.4,2965 1360,2965 1403,2922 1431,2922 1460,2893 1687,2893 1750,2830 1750,2539.86 1730,2519.86 1730,2455.86 1570,2295.86 1570,2180 1577,2173 1577,2132.72 v1(1586.14,2123.58)
LAN0_C-: D55.C D83.3 J22.6 R424.2 | length 2150.7
  TOP w4: v1(1197.4,2945) D83.3@1197.4,2906.85 1216.85,2906.85 1220,2910 1220,2950 1225,2955 1240,2955 1245,2950 1245,2911.82 D55.C@1253,2903.82 1260,2910.82 1260,2950 1265,2955 1275,2955 1295,2975 1295,3039.14 1279.14,3055 1249,3055 1245,3059 1245,3076 1249,3080 1284.14,3080 1305,3100.86 1305,3170 1263.28,3211.72 1228.28,3211.72 J22.6@1205,3235 ; v1(1559,2124) 1568,2115 1568,2104.86 1577.86,2095 1597.86,2095 1606,2086.86 1606,2083.72 R424.2@1595,2072.72
  BOTTOM w4: v1(1197.4,2945) 1207.4,2955 1355.86,2955 1398.86,2912 1426.86,2912 1455.86,2883 1682.86,2883 1740,2825.86 1740,2544 1720,2524 1720,2460 1560,2300 1560,2175.86 1567,2168.86 1567,2132 v1(1559,2124)
LAN0_D+: D54.A D83.6 J22.8 R215.2 | length 2159.5
  TOP w4: J22.8@1105,3235 1090.87,3220.87 1090.87,3182.12 1110,3163 1110,3100 1120,3090 1155.14,3090 1165,3080.14 1165,3054.86 1155.14,3045 1055,3045 1047,3037 1047,2970.14 1052.14,2965 1055,2965 1060,2970 1060,2999.18 D54.A@1067,3006.18 1075,2998.18 1075,2970 1080,2965 1105,2965 1115,2975 1115,3005.55 D83.6@1122.6,3013.15 1130,3005.75 1130,2986.6 1142.6,2974 v1(1147.6,2974) ; R215.2@1525,2072.72 1511.26,2086.46 1511.26,2092.12 1540,2120.86 1540,2151 v1(1548.65,2159.65)
  BOTTOM w4: v1(1147.6,2974) 1157.6,2964 1168,2964 1178,2954 1178,2929.4 1190.4,2917 1353,2917 1377,2893 1418,2893 1447,2864 1671,2864 1720,2815 1720,2551.86 1701,2532.86 1701,2470 1540,2309 1540,2168.29 v1(1548.65,2159.65)
LAN0_D-: D54.C D83.1 J22.9 R214.2 | length 2156.1
  TOP w4: J22.9@1055,3135 1055,3142 1082.1,3169.1 1089.76,3169.1 1100,3158.86 1100,3095.86 1115.86,3080 1151,3080 1155,3076 1155,3059 1151,3055 1050.86,3055 1037,3041.14 1037,2966 1048,2955 1055,2955 1060,2950 1060,2910.82 D54.C@1067,2903.82 1075,2911.82 1075,2950 1080,2955 1105,2955 1115,2945 1115,2914.45 D83.1@1122.6,2906.85 1130,2914.25 1130,2931.4 1142.6,2944 v1(1147.6,2944) ; R214.2@1485,2072.72 1501.26,2088.98 1501.26,2096.26 1530,2125 1530,2151 v1(1521.36,2159.65)
  BOTTOM w4: v1(1147.6,2944) 1157.6,2954 1163.86,2954 1168,2949.86 1168,2925.26 1186.26,2907 1348.86,2907 1372.86,2883 1413.86,2883 1442.86,2854 1666.86,2854 1710,2810.86 1710,2556 1691,2537 1691,2474.14 1530,2313.14 1530,2168.29 v1(1521.36,2159.65)
LAN1_A+: D61.A D82.4 J23.2 R266.2 | length 2843.4
  TOP w4: J23.2@2145,3235 2165,3235 2185,3215 2185,3194 2176,3185 2112.39,3185 2100,3197.39 2100,3250.86 2124.14,3275 2165.86,3275 2250,3190.86 2250,2964 2246,2960 2240,2960 2237.11,2962.89 2237.11,3000.07 D61.A@2231,3006.18 2225,3000.18 2225,2965 2220,2960 2182.4,2960 v1(2172.4,2970) D82.4@2172.4,3010.15 ; v1(2693.65,2277) 2686,2269.35 2686,2265.14 2696.14,2255 2715.14,2255 2744,2226.14 2744,2185.14 2803.5,2125.64 2803.5,2086.22 R266.2@2817,2072.72
  BOTTOM w4: v1(2172.4,2970) 2182.4,2960 2190,2960 2195,2965 2195,3005.86 2174.86,3026 2016,3026 1960,2970 1960,2910.86 1940,2890.86 1940,2585 1968,2557 2324.86,2557 2343.86,2576 2568.14,2576 2650,2494.14 2650,2410 2685,2375 2685,2285.65 v1(2693.65,2277)
LAN1_A-: D61.C D82.3 J23.3 R265.2 | length 2845.1
  TOP w4: J23.3@2095,3135 2100,3140 2100,3183.25 2090,3193.25 2090,3255 2120,3285 2170,3285 2260,3195 2260,2959.86 2250.14,2950 2240,2950 2236.77,2946.77 2236.77,2909.59 D61.C@2231,2903.82 2225,2909.82 2225,2945 2220,2950 2182.4,2950 v1(2172.4,2940) D82.3@2172.4,2903.85 ; v1(2666.36,2277) 2676,2267.36 2676,2261 2692,2245 2711,2245 2734,2222 2734,2181 2793.5,2121.5 2793.5,2086.22 R265.2@2780,2072.72
  BOTTOM w4: v1(2172.4,2940) 2182.4,2950 2194.14,2950 2205,2960.86 2205,3010 2179,3036 2011.86,3036 1950,2974.14 1950,2915 1930,2895 1930,2580.86 1963.86,2547 2329,2547 2348,2566 2564,2566 2640,2490 2640,2405.86 2675,2370.86 2675,2285.64 v1(2666.36,2277)
LAN1_B+: D60.A D82.6 J23.4 R264.2 | length 2855.5
  TOP w4: D82.6@2097.6,3010.15 v1(2097.6,2970) 2087.6,2960 2050,2960 2045,2965 2045,3001.18 D60.A@2040,3006.18 2035,3001.18 2035,2965 2030,2960 2024.14,2960 2020,2964.14 2020,3035.86 2029.14,3045 2219.14,3045 2230,3055.86 2230,3079.14 2219.14,3090 2154.14,3090 2150,3094.14 2150,3156.36 v1(2158.64,3165) ; v1(2689.07,2214) 2680.43,2205.35 2680.43,2199.57 2695.19,2184.81 2695.19,2087.53 R264.2@2710,2072.72
  BOTTOM w4: J23.4@2045,3235 2045,3255 2030,3270 1990,3270 1985,3265 1985,3200 1993,3192 2141,3192 2150,3183 2150,3173.64 v1(2158.64,3165) ; v1(2097.6,2970) 2107.6,2960 2113,2960 2118,2965 2118,2987.86 2108.86,2997 2032,2997 1995,2960 1995,2900.86 1969,2874.86 1969,2600.14 1983.14,2586 2311.86,2586 2330.86,2605 2585,2605 2680,2510 2680,2424.14 2727,2377.14 2727,2257 2710,2240 2695.14,2240 2680.5,2225.36 2680.5,2222.57 v1(2689.07,2214)
LAN1_B-: D60.C D82.1 J23.7 R263.2 | length 2854.3
  TOP w4: D82.1@2097.6,2903.85 v1(2097.6,2940) 2087.6,2950 2050,2950 2045,2945 2045,2908.82 D60.C@2040,2903.82 2035,2908.82 2035,2945 2030,2950 2020,2950 2010,2960 2010,3040 2025,3055 2215,3055 2220,3060 2220,3075 2215,3080 2150,3080 2140,3090 2140,3156.35 v1(2131.35,3165) ; v1(2661.78,2214) 2670.43,2205.36 2670.43,2195.43 2685.19,2180.67 2685.19,2087.91 R263.2@2670,2072.72
  BOTTOM w4: J23.7@1895,3135 1942,3182 2136.86,3182 2140,3178.86 2140,3173.65 v1(2131.35,3165) ; v1(2097.6,2940) 2107.6,2950 2117.14,2950 2128,2960.86 2128,2992 2113,3007 2027.86,3007 1985,2964.14 1985,2905 1959,2879 1959,2596 1979,2576 2316,2576 2335,2595 2580.86,2595 2670,2505.86 2670,2420 2717,2373 2717,2261.14 2705.86,2250 2691,2250 2670.5,2229.5 2670.5,2222.72 v1(2661.78,2214)
LAN1_C+: D59.A D81.4 J23.5 R262.2 | length 2813
  TOP w4: D81.4@1902.4,3008.15 v1(1902.4,2970) 1912.4,2960 1950,2960 1955,2965 1955,3001.18 D59.A@1960,3006.18 1965,3001.18 1965,2965 1970,2960 1975.86,2960 1980,2964.14 1980,3040 1975,3045 1920.86,3045 1910,3055.86 1910,3084.14 1920.43,3094.57 2030.43,3094.57 2040,3104.14 2040,3175 2030.15,3184.85 1969.85,3184.85 1965,3180 1965,3165 J23.5@1995,3135 ; R262.2@2635,2072.72 2622.5,2085.22 2622.5,2093.5 2595,2121 2595,2150.86 2599.14,2155 2605.86,2155 2620,2140.86 2620,2125 2625,2120 2638.03,2106.97 2651.97,2106.97 2665,2120 2665,2170 2650,2185 2634.14,2185 2627,2192.14 2627,2206 v1(2635,2214)
  BOTTOM w4: v1(1902.4,2970) 1912.4,2960 1920,2960 1931,2949 1931,2926 1911,2906 1911,2883.87 1901.14,2874.01 1897,2874.01 1893,2870.01 1893,2862.01 1897,2858.01 1901.14,2858.01 1911,2848.16 1911,2831.87 1901.14,2822.01 1897,2822.01 1893,2818.01 1893,2810.01 1897,2806.01 1901.14,2806.01 1911,2796.16 1911,2779.87 1901.14,2770.01 1897,2770.01 1893,2766.01 1893,2758.01 1897,2754.01 1901.14,2754.01 1911,2744.16 1911,2727.87 1901.14,2718.01 1897,2718.01 1893,2714.01 1893,2706.01 1897,2702.01 1901.14,2702.01 1911,2692.16 1911,2675.87 1901.14,2666.01 1897,2666.01 1893,2662.01 1893,2654.01 1897,2650.01 1901.14,2650.01 1911,2640.16 1911,2623.87 1901.14,2614.01 1897,2614.01 1893,2610.01 1893,2602.01 1897,2598.01 1901.14,2598.01 1911,2588.16 1911,2569 1952,2528 2337.86,2528 2356.86,2547 2553,2547 2583,2517 2583,2492.14 2590.14,2485 2610,2485 2620,2475 2620,2450 2610,2440 2589,2440 2585,2436 2585,2420 2590,2415 2610,2415 2620,2405 2620,2384 2606,2370 2590,2370 2585,2365 2585,2349.14 2589.14,2345 2615,2345 2629.53,2359.53 2643.47,2359.53 2656,2347 2656,2330 2639,2313 2639,2289 2625,2275 2625,2224 v1(2635,2214)
LAN1_C-: D59.C D81.3 J23.6 R261.2 | length 2815.4
  TOP w4: D81.3@1902.4,2901.85 v1(1902.4,2940) 1912.4,2950 1950.14,2950 1955.07,2945.07 1955.07,2908.75 D59.C@1960,2903.82 1965,2908.82 1965,2945 1970,2950 1980,2950 1990,2960 1990,3044.14 1979.14,3055 1925,3055 1920,3060 1920,3080 1924.57,3084.57 2034.57,3084.57 2050,3100 2050,3179.14 2034.3,3194.85 1970.15,3194.85 1945,3220 J23.6@1945,3235 ; R261.2@2600,2072.72 2612.5,2085.22 2612.5,2089.36 2585,2116.86 2585,2155 2595,2165 2610,2165 2630,2145 2630,2129.14 2642.17,2116.97 2647.83,2116.97 2655,2124.14 2655,2165.86 2645.86,2175 2630,2175 2617,2188 2617,2204.36 v1(2607.36,2214)
  BOTTOM w4: v1(1902.4,2940) 1912.4,2950 1915.86,2950 1921,2944.86 1921,2930.14 1901,2910.14 1901,2888.01 1897,2884.01 1892.86,2884.01 1883,2874.16 1883,2857.87 1892.86,2848.01 1897,2848.01 1901,2844.01 1901,2836.01 1897,2832.01 1892.86,2832.01 1883,2822.16 1883,2805.87 1892.86,2796.01 1897,2796.01 1901,2792.01 1901,2784.01 1897,2780.01 1892.86,2780.01 1883,2770.16 1883,2753.87 1892.86,2744.01 1897,2744.01 1901,2740.01 1901,2732.01 1897,2728.01 1892.86,2728.01 1883,2718.16 1883,2701.87 1892.86,2692.01 1897,2692.01 1901,2688.01 1901,2680.01 1897,2676.01 1892.86,2676.01 1883,2666.16 1883,2649.87 1892.86,2640.01 1897,2640.01 1901,2636.01 1901,2628.01 1897,2624.01 1892.86,2624.01 1883,2614.16 1883,2597.87 1892.86,2588.01 1897,2588.01 1901,2584.01 1901,2564.86 1947.86,2518 2342,2518 2361,2537 2548.86,2537 2573,2512.86 2573,2488 2586,2475 2605.86,2475 2610,2470.86 2610,2454.14 2605.86,2450 2584.86,2450 2575,2440.14 2575,2415.86 2585.86,2405 2605.86,2405 2610,2400.86 2610,2388.14 2601.86,2380 2585.86,2380 2575,2369.14 2575,2345 2585,2335 2619.14,2335 2633.67,2349.53 2639.33,2349.53 2646,2342.86 2646,2334.14 2629,2317.14 2629,2293.14 2615,2279.14 2615,2221.64 v1(2607.36,2214)
LAN1_D+: D58.A D81.6 J23.8 R260.2 | length 2786.9
  TOP w4: D81.6@1827.6,3008.15 v1(1827.6,2970) 1817.6,2960 1779.66,2960 1774.83,2964.83 1774.83,3001.36 D58.A@1770,3006.18 1762.83,2999.01 1762.83,2963.18 1759.66,2960 1754,2960 1750,2964 1750,3070.86 1759.14,3080 1805,3080 1845,3040 1864.14,3040 1880,3055.86 1880,3079.14 1850,3109.14 1850,3166.03 1830,3186.03 1830,3220 J23.8@1845,3235 ; R260.2@2533,2072.72 2521,2084.72 2521,2099.14 2510.14,2110 2494.14,2110 2490,2114.14 2490,2125.86 2494.14,2130 2530.14,2130 2540,2139.86 2540,2165.14 2530.14,2175 2494.14,2175 2490,2179.14 2490,2195 2495,2200 2508,2200 2526,2218 2535,2218 2535.54,2217.46 v1(2538.46,2217.46)
  BOTTOM w4: v1(1827.6,2970) 1837.29,2960.09 1846.99,2959.98 1866,2940.97 1866,2569 1936,2499 2345.86,2499 2364.86,2518 2522.15,2518 2553,2487.14 2553,2409.86 2543.14,2400 2519.14,2400 2515,2395.86 2515,2379.14 2519.14,2375 2528.34,2375 2538.2,2365.14 2538.2,2351.2 2517,2330 2363,2330 2359,2326 2359,2314 2363,2310 2515,2310 2562.6,2262.4 2562.6,2248.46 2548.1,2233.96 2548.1,2223.26 2542.3,2217.46 v1(2538.46,2217.46)
LAN1_D-: D58.C D81.1 J23.9 R259.2 | length 2788.2
  TOP w4: J23.9@1795,3135 1795,3165 1810,3180 1821.88,3180 1823.8,3178.08 1840,3161.88 1840,3105 1870,3075 1870,3060 1860,3050 1849.14,3050 1809.14,3090 1755,3090 1740,3075 1740,2959.86 1749.86,2950 1759.66,2950 1762.82,2946.84 1762.82,2911 D58.C@1770,2903.82 1774.76,2908.57 1774.76,2945.24 1779.51,2950 1817.26,2950 v1(1827.26,2940) 1827.6,2939.66 D81.1@1827.6,2901.85 ; R259.2@2499,2072.72 2511,2084.72 2511,2095 2506,2100 2490,2100 2480,2110 2480,2130 2490,2140 2526,2140 2530,2144 2530,2161 2526,2165 2490,2165 2480,2175 2480,2199.14 2490.86,2210 2503.86,2210 2518.14,2224.29 2518.14,2235.76 v1(2519.15,2236.77)
  BOTTOM w4: v1(1827.26,2940) 1837.57,2950.08 1842.81,2950.02 1856,2936.83 1856,2564.86 1931.86,2489 2350,2489 2369,2508 2518,2508 2543,2483 2543,2414 2539,2410 2515,2410 2505,2400 2505,2375 2515,2365 2524.2,2365 2528.2,2361 2528.2,2355.35 2512.86,2340 2358.86,2340 2349,2330.14 2349,2309.86 2358.86,2300 2510.86,2300 2552.6,2258.26 2552.6,2252.6 2538,2238 2520.39,2238 v1(2519.15,2236.77)
LVDS_EN_GPIO3_A2: J2.65 R137.2 | length 3693.6
  TOP w5: R137.2@1509,762.72 1632.28,762.72 1695,700 1780,700 v1(1782,698) ; v1(3038,2655) 3038,2659 3054.72,2675.72 J2.65@3054.72,2706.42
  BOTTOM w5: v1(1782,698) 1782,781 1787,786 1787,1012 1862.97,1087.97 1948.58,1087.97 1958,1078.55 1958,1022 1966.09,1013.91 1966.17,1013.91 1979.08,1001 2074.14,1001 2126,1052.86 2126,1071 2161,1106 2241,1106 2300,1165 2300,1345 2260,1385 2260,1745 2235,1770 2235,1895 2308,1968 2308,2018 2351.67,2061.67 2351.67,2091.59 2366.41,2106.33 2380.53,2106.33 2462,2024.86 2859,2024.86 2859.14,2025 2860,2025 2965,2130 2965,2670 2975,2680 3015,2680 3038,2657 v1(3038,2655)
LVDS_ON_: J18.4 Q7.2 R133.2 R135.2 | length 1478.2
  TOP w5: v1(1537,368) 1522,383 1522,600 1546,624 1546,677 1574,705 1574,717 1598,741 v1(1610,741) ; Q7.2@1614.68,952.5 1614.68,960 1619.68,965 1634,965 v1(1637,962) 1640,965 1662.28,965 R135.2@1672.28,975 1690,957.28 1690,952.72 R133.2@1707.72,935
  BOTTOM w5: J18.4@874.37,405 918.37,361 1532,361 1537,366 v1(1537,368) ; v1(1610,741) 1598,753 1598,833 1625,860 1625,913 1637,925 v1(1637,962)
LVDS_ON_GPIO3_A1: J2.67 Q7.3 R132.2 R135.1 | length 4881.7
  TOP w5: R135.1@1707.72,975 R132.2@1707.72,1013 ; R132.2@1710,1015.28 R132.2@1707.72,1013 ; v1(2320,1330) 2276.43,1330 2210,1263.57 2210,1200 2145,1135 2015,1135 2002,1122 1869,1122 1852,1139 1791,1139 1728.5,1076.5 1684.5,1076.5 1653,1045 1607,1045 1595,1033 Q7.3@1595,1015.5 1625.5,1015.5 1639,1002 1696.72,1002 R132.2@1707.72,1013 ; v1(3016,2757) 3016,2756.03 3035.03,2737 J2.67@3035.03,2706.42 ; v1(3669,1736) 3669,1751 3640,1780 3640,1945 3610,1975 3610,2220 3745,2355 v1(3759,2355)
  BOTTOM w5: v1(2320,1330) 2335,1345 2970,1345 3395,1770 3635,1770 v1(3669,1736) ; v1(3016,2757) 3016,2786 3025,2795 3040,2795 3101,2856 3425,2856 3455,2826 3522,2826 3557.5,2790.5 3557.5,2755.5 3587,2726 3906,2726 3938,2694 3938,2613 3794,2469 3794,2404 3755.54,2365.54 3755.54,2358.46 v1(3759,2355)
LVDS_PWM13: J18.3 R138.2 U14.4 | length 1380.4
  TOP w5: U14.4@1508.31,804.41 1525,804.41 v1(1540,819.41) 1556.87,819.41 R138.2@1562.28,814 ; v1(1565,359) 1565,374 1535,404 1535,595 1558,618 1558,672 v1(1596,710)
  BOTTOM w5: J18.3@795.63,405 851.63,349 1555,349 v1(1565,359) ; v1(1540,819.41) 1588,771.41 1588,718 v1(1596,710)
LVDS_TX0_CLKN: J16.15 R127.2 | length 749.8
  TOP w4: J16.15@570,1998.78 537.63,1998.78 530,1991.15 530,1973.14 538.14,1965 614.14,1965 625,1954.14 625,1904.14 629.14,1900 640.86,1900 645,1904.14 645,1965.14 654.86,1975 673.14,1975 710,1938.14 710,1899.14 v1(722.65,1886.5)
  BOTTOM w4: v1(722.65,1886.5) 710,1873.85 710,1835 748,1797 929.28,1797 R127.2@942.28,1810
LVDS_TX0_CLKP: J16.16 R126.2 | length 751.7
  TOP w4: J16.16@491.26,1998.78 507.22,1998.78 520,1986 520,1969 534,1955 610,1955 615,1950 615,1900 625,1890 645,1890 655,1900 655,1961 659,1965 669,1965 700,1934 700,1899.14 v1(687.36,1886.5)
  BOTTOM w4: v1(687.36,1886.5) 700,1873.85 700,1830.86 743.86,1787 930.28,1787 R126.2@942.28,1775
LVDS_TX0_D0N: J16.7 R122.8 | length 788.8
  TOP w4: J16.7@570,1683.82 534.63,1683.82 530.63,1679.82 530.63,1662.37 542,1651 791.86,1651 815,1674.14 815,1735 812.07,1737.93 798,1752 798,1924.19 807.86,1934.05 811.05,1934.05 v1(827,1950)
  BOTTOM w4: v1(827,1950) 827,1949 839,1937 849,1937 878.33,1907.67 931.67,1907.67 937.5,1913.5 R122.8@941.32,1913.5
LVDS_TX0_D0P: J16.8 R122.7 | length 787.8
  TOP w4: J16.8@491.26,1683.82 509.18,1683.82 520.63,1672.37 520.63,1658.23 537.86,1641 796,1641 825,1670 825,1739.14 822.07,1742.07 808,1756.14 808,1920.05 812,1924.05 817.66,1924.05 v1(827,1914.71)
  BOTTOM w4: v1(827,1914.71) 839.79,1927.5 844.36,1927.5 874.19,1897.67 931.33,1897.67 937.16,1891.84 R122.7@941.32,1891.84
LVDS_TX0_D1N: J16.9 R122.6 | length 782.8
  TOP w4: J16.9@570,1762.56 534.56,1762.56 529,1757 529,1733 534,1728 598,1728 610,1740 610,1755 620,1765 645,1765 655,1755 655,1694 659,1690 675,1690 680,1695 680,1721 690,1731 706.86,1731 720,1744.14 720,1858.14 729.86,1868 741.35,1868 v1(750,1876.65)
  BOTTOM w4: v1(750,1876.65) 759.15,1867.5 789.14,1867.5 800,1856.64 800,1839.14 804.14,1835 836,1835 840,1839 840,1852.64 855.36,1868 932,1868 936.16,1872.16 R122.6@941.32,1872.16
LVDS_TX0_D1P: J16.10 R122.5 | length 781.3
  TOP w4: J16.10@491.26,1762.56 506.44,1762.56 519,1750 519,1728.86 529.86,1718 602.14,1718 620,1735.86 620,1750.86 624.14,1755 640.86,1755 645,1750.86 645,1689.86 654.86,1680 679.14,1680 690,1690.86 690,1716.86 694.14,1721 711,1721 730,1740 730,1854 734,1858 741.36,1858 v1(750,1849.36)
  BOTTOM w4: v1(750,1849.36) 758.14,1857.5 785,1857.5 790,1852.5 790,1835 800,1825 840.14,1825 850,1834.86 850,1848.5 857.5,1856 933,1856 938.5,1850.5 R122.5@941.32,1850.5
LVDS_TX0_D2N: J16.11 R123.8 | length 770.6
  TOP w4: J16.11@570,1841.3 533.63,1841.3 529.63,1837.3 529.63,1817.51 538.14,1809 604.86,1809 615,1819.14 615,1860.14 624.86,1870 650,1870 660,1860 660,1799.14 664.14,1795 685.21,1795 v1(693.92,1803.72)
  BOTTOM w4: v1(693.92,1803.72) 705.29,1792.35 710.65,1792.35 721.93,1781.07 721.93,1732.07 726.5,1727.5 741,1727.5 745,1731.5 745,1754.14 755.86,1765 775.14,1765 787,1753.14 787,1732.14 791.64,1727.5 803.36,1727.5 810,1734.14 810,1755.14 819.86,1765 840,1765 850,1755 850,1732.5 854.5,1728 927,1728 933.5,1734.5 R123.8@939.32,1734.5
